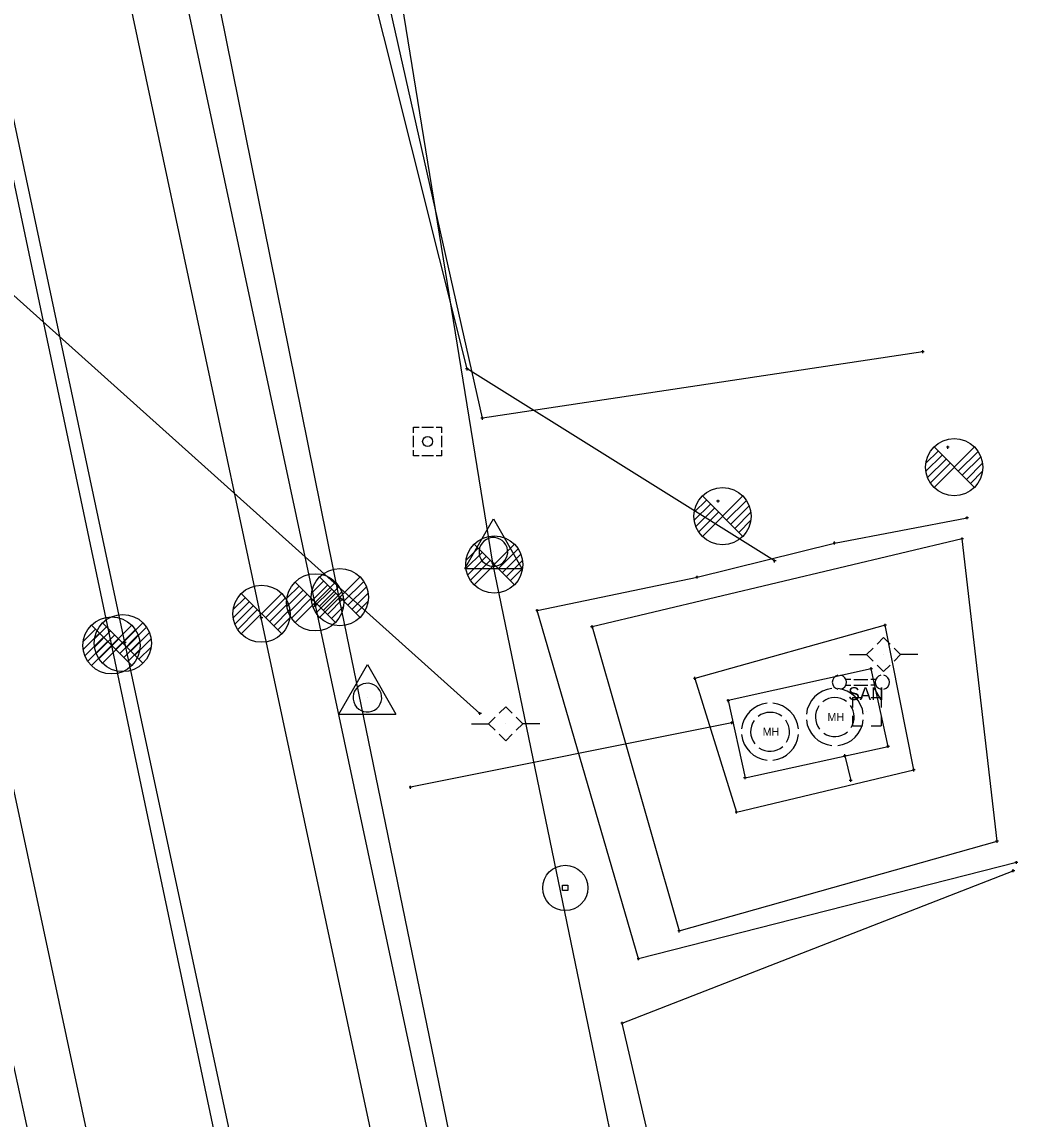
# Model space of a CAD drawing. Extents: x 1954856 to 2011933, y 399149 to 426294.
# Drawn here: x 2006043.9 to 2006132.7, y 402947.5 to 403043.4 of the extents above; entities that cross this region are included whole.
import ezdxf

# ---------------------------------------------------------------- set-up
doc = ezdxf.new("R2010")
doc.units = 0
for name, color, linetype in [('BankMent_ep', 7, 'Continuous'), ('BaselineSurvey', 7, 'Continuous'), ('ConcSlabs_ep', 7, 'Continuous'), ('ElecAer_ep', 7, 'Continuous'), ('Fence_ep', 7, 'Continuous'), ('Gates_ep', 7, 'Continuous'), ('ManholeUnknown_ep', 7, 'Continuous'), ('MonumentIRC_ep', 7, 'Continuous'), ('MonumentPIP_ep', 7, 'Continuous'), ('PavtAsphalt_ep', 7, 'Continuous'), ('PavtAsphaltCrown_ep', 7, 'Continuous'), ('PointLocator_ep', 7, 'Continuous'), ('PoleElec_ep', 7, 'Continuous'), ('PullBox_ep', 7, 'Continuous'), ('SanitarySewerB_ep', 7, 'Continuous'), ('ShldrPaved_ep', 7, 'Continuous'), ('TelePed_ep', 7, 'Continuous'), ('TreeLineWoods_ep', 7, 'Continuous'), ('VentSewer_ep', 7, 'Continuous'), ('XSPt_ep', 7, 'Continuous')]:
    doc.layers.add(name, color=color, linetype=linetype)

msp = doc.modelspace()

# ---------------------------------------------------------------- linework, layer by layer
at = {"layer": 'BankMent_ep'}
for points in [[(2006123.672, 402765.11), (2006120.281, 402798.882), (2006114.638, 402841.007), (2006105.234, 402898.319), (2006085.025, 402996.113), (2006069.006, 403095.019), (2006055.498, 403136.901)], [(2006121.666, 402755.96), (2006112.717, 402797.088), (2006091.828, 402894.752), (2006071.624, 402992.958), (2006051.855, 403090.735), (2006044.44, 403133.564)]]:
    msp.add_lwpolyline(points, dxfattribs=at)
for points in [[(2006093.704, 402990.551), (2006101.326, 402963.953), (2006129.111, 402971.79), (2006126.062, 402998.239)], [(2006102.683, 402986.036), (2006106.328, 402974.34), (2006121.837, 402978.026), (2006119.328, 402990.679)]]:
    msp.add_lwpolyline(points, close=True, dxfattribs=at)
at = {"layer": 'BaselineSurvey'}
msp.add_line((2006223.925, 402174.382), (2005094.479, 407516.047), dxfattribs=at)
msp.add_line((2006223.925, 402174.382), (2005094.479, 407516.047), dxfattribs=at)
at = {"layer": 'ConcSlabs_ep'}
msp.add_lwpolyline([(2006105.61, 402984.094), (2006107.079, 402977.35), (2006119.584, 402980.083), (2006118.106, 402986.881)], close=True, dxfattribs=at)
at = {"layer": 'ElecAer_ep'}
msp.add_lwpolyline([(2006062.406, 402767.04), (2006002.661, 403055.822), (2006083.898, 402982.967)], dxfattribs=at)
at = {"layer": 'Fence_ep'}
for points in [[(2006114.898, 402997.864), (2006126.489, 403000.07)], [(2006130.798, 402969.942), (2006097.759, 402961.511), (2006088.912, 402991.959), (2006102.89, 402994.885)]]:
    msp.add_lwpolyline(points, dxfattribs=at)
at = {"layer": 'Gates_ep'}
msp.add_lwpolyline([(2006102.89, 402994.885), (2006114.898, 402997.864)], dxfattribs=at)
at = {"layer": 'ManholeUnknown_ep'}
for p, q in [((2006114.927, 402982.652), (2006114.927, 402982.652)), ((2006109.265, 402981.366), (2006109.265, 402981.366))]:
    msp.add_line(p, q, dxfattribs=at)
for centre, radius, start, end in [((2006114.927, 402982.652), 2.5, 95.73916, 174.26084), ((2006114.927, 402982.652), 2.5, 5.73916, 84.26084), ((2006109.265, 402981.366), 2.5, 95.73916, 174.26084), ((2006109.265, 402981.366), 2.5, 5.73916, 84.26084), ((2006114.927, 402982.652), 1.7, 144.52453, 218.27924), ((2006114.927, 402982.652), 1.7, 53.11695, 127.61151), ((2006114.927, 402982.652), 1.7, 327.53021, 36.20393), ((2006109.265, 402981.366), 1.7, 53.11695, 127.61151), ((2006109.265, 402981.366), 1.7, 144.52453, 218.27924), ((2006109.265, 402981.366), 1.7, 327.53021, 36.20393), ((2006114.927, 402982.652), 2.5, 185.73916, 264.26084), ((2006114.927, 402982.652), 2.5, 275.73916, 354.26084), ((2006109.265, 402981.366), 2.5, 185.73916, 264.26084), ((2006109.265, 402981.366), 2.5, 275.73916, 354.26084), ((2006114.927, 402982.652), 1.7, 235.19226, 310.61719), ((2006109.265, 402981.366), 1.7, 235.19226, 310.61719)]:
    msp.add_arc(centre, radius, start, end, dxfattribs=at)
at = {"layer": 'MonumentIRC_ep'}
for p, q in [((2006082.573, 402995.651), (2006085.073, 402999.981)), ((2006085.073, 402999.981), (2006087.573, 402995.651)), ((2006085.073, 402997.094), (2006085.073, 402997.094)), ((2006082.573, 402995.651), (2006087.573, 402995.651)), ((2006071.559, 402982.91), (2006074.059, 402987.24)), ((2006074.059, 402987.24), (2006076.559, 402982.91)), ((2006074.059, 402984.353), (2006074.059, 402984.353)), ((2006071.559, 402982.91), (2006076.559, 402982.91))]:
    msp.add_line(p, q, dxfattribs=at)
for centre in [(2006085.073, 402997.094), (2006074.059, 402984.353)]:
    msp.add_arc(centre, 1.255, 209.92943, 209.02995, dxfattribs=at)
at = {"layer": 'MonumentPIP_ep'}
msp.add_line((2006091.361, 402967.713), (2006091.361, 402967.713), dxfattribs=at)
msp.add_lwpolyline([(2006091.129, 402967.481), (2006091.129, 402967.945), (2006091.593, 402967.945), (2006091.593, 402967.481)], close=True, dxfattribs=at)
msp.add_circle((2006091.361, 402967.713), 1.977, dxfattribs=at)
at = {"layer": 'PavtAsphalt_ep'}
msp.add_line((2006061.812, 402888.943), (2006040.75, 402987.463), dxfattribs=at)
msp.add_lwpolyline([(2006233.389, 402199.404), (2006231.307, 402208.776), (2006210.298, 402306.906), (2006189.726, 402404.406), (2006168.519, 402502.437), (2006147.449, 402600.546), (2006127.002, 402698.201), (2006106.479, 402795.475), (2006085.7, 402893.48), (2006064.781, 402991.322), (2006043.91, 403089.283), (2006023.047, 403187.504), (2006002.574, 403285.226), (2005981.704, 403382.697), (2005961.207, 403480.496), (2005940.446, 403578.305), (2005919.871, 403676.233), (2005898.845, 403774.26)], dxfattribs=at)
at = {"layer": 'PavtAsphaltCrown_ep'}
msp.add_lwpolyline([(2006221.576, 402197.041), (2006219.373, 402206.688), (2006198.419, 402304.427), (2006177.674, 402402.212), (2006156.488, 402500.143), (2006135.917, 402597.882), (2006115.394, 402695.489), (2006094.3, 402793.442), (2006073.801, 402891.433), (2006052.859, 402989.16), (2006032.075, 403086.962), (2006011.062, 403184.663), (2005990.583, 403282.628), (2005969.857, 403380.234), (2005949.302, 403478.326), (2005928.678, 403576.103), (2005908.104, 403674.029), (2005887.142, 403771.84)], dxfattribs=at)
at = {"layer": 'PointLocator_ep'}
for p, q in [((2006122.736, 403014.593), (2006122.486, 403014.593)), ((2006122.611, 403014.468), (2006122.611, 403014.718)), ((2006122.611, 403014.593), (2006122.611, 403014.593)), ((2006082.774, 403012.96), (2006082.774, 403013.21)), ((2006082.899, 403013.085), (2006082.649, 403013.085)), ((2006082.774, 403013.085), (2006082.774, 403013.085)), ((2006084.237, 403008.778), (2006083.987, 403008.778)), ((2006084.112, 403008.653), (2006084.112, 403008.903)), ((2006084.112, 403008.778), (2006084.112, 403008.778)), ((2006124.936, 403006.237), (2006124.686, 403006.237)), ((2006124.811, 403006.112), (2006124.811, 403006.362)), ((2006124.811, 403006.237), (2006124.811, 403006.237)), ((2006104.843, 403001.53), (2006104.593, 403001.53)), ((2006104.718, 403001.405), (2006104.718, 403001.655)), ((2006104.718, 403001.53), (2006104.718, 403001.53)), ((2006126.614, 403000.07), (2006126.364, 403000.07)), ((2006126.489, 402999.945), (2006126.489, 403000.195)), ((2006126.489, 403000.07), (2006126.489, 403000.07)), ((2006115.023, 402997.864), (2006114.773, 402997.864)), ((2006114.898, 402997.739), (2006114.898, 402997.989)), ((2006114.898, 402997.864), (2006114.898, 402997.864)), ((2006126.187, 402998.239), (2006125.937, 402998.239)), ((2006126.062, 402998.114), (2006126.062, 402998.364)), ((2006126.062, 402998.239), (2006126.062, 402998.239)), ((2006085.15, 402996.113), (2006084.9, 402996.113)), ((2006085.025, 402995.988), (2006085.025, 402996.238)), ((2006085.025, 402996.113), (2006085.025, 402996.113)), ((2006109.787, 402996.303), (2006109.537, 402996.303)), ((2006109.662, 402996.178), (2006109.662, 402996.428)), ((2006109.662, 402996.303), (2006109.662, 402996.303)), ((2006102.89, 402994.76), (2006102.89, 402995.01)), ((2006103.015, 402994.885), (2006102.765, 402994.885)), ((2006102.89, 402994.885), (2006102.89, 402994.885)), ((2006071.624, 402992.833), (2006071.624, 402993.083)), ((2006069.654, 402992.446), (2006069.404, 402992.446)), ((2006069.529, 402992.321), (2006069.529, 402992.571)), ((2006069.529, 402992.446), (2006069.529, 402992.446)), ((2006071.749, 402992.958), (2006071.499, 402992.958)), ((2006071.624, 402992.958), (2006071.624, 402992.958)), ((2006088.912, 402991.834), (2006088.912, 402992.084)), ((2006064.906, 402991.322), (2006064.656, 402991.322)), ((2006064.781, 402991.197), (2006064.781, 402991.447)), ((2006064.781, 402991.322), (2006064.781, 402991.322)), ((2006089.037, 402991.959), (2006088.787, 402991.959)), ((2006088.912, 402991.959), (2006088.912, 402991.959)), ((2006093.829, 402990.551), (2006093.579, 402990.551)), ((2006093.704, 402990.426), (2006093.704, 402990.676)), ((2006093.704, 402990.551), (2006093.704, 402990.551)), ((2006119.453, 402990.679), (2006119.203, 402990.679)), ((2006119.328, 402990.554), (2006119.328, 402990.804)), ((2006119.328, 402990.679), (2006119.328, 402990.679)), ((2006052.859, 402989.035), (2006052.859, 402989.285)), ((2006052.984, 402989.16), (2006052.734, 402989.16)), ((2006052.859, 402989.16), (2006052.859, 402989.16)), ((2006118.231, 402986.881), (2006117.981, 402986.881)), ((2006118.106, 402986.756), (2006118.106, 402987.006)), ((2006118.106, 402986.881), (2006118.106, 402986.881)), ((2006102.808, 402986.036), (2006102.558, 402986.036)), ((2006102.683, 402985.911), (2006102.683, 402986.161)), ((2006102.683, 402986.036), (2006102.683, 402986.036)), ((2006105.735, 402984.094), (2006105.485, 402984.094)), ((2006105.61, 402983.969), (2006105.61, 402984.219)), ((2006105.61, 402984.094), (2006105.61, 402984.094)), ((2006084.023, 402982.967), (2006083.773, 402982.967)), ((2006083.898, 402982.842), (2006083.898, 402983.092)), ((2006083.898, 402982.967), (2006083.898, 402982.967)), ((2006106.042, 402982.146), (2006105.792, 402982.146)), ((2006105.917, 402982.021), (2006105.917, 402982.271)), ((2006105.917, 402982.146), (2006105.917, 402982.146)), ((2006119.709, 402980.083), (2006119.459, 402980.083)), ((2006119.584, 402979.958), (2006119.584, 402980.208)), ((2006119.584, 402980.083), (2006119.584, 402980.083)), ((2006115.934, 402979.272), (2006115.684, 402979.272)), ((2006115.809, 402979.147), (2006115.809, 402979.397)), ((2006115.809, 402979.272), (2006115.809, 402979.272)), ((2006121.962, 402978.026), (2006121.712, 402978.026)), ((2006121.837, 402977.901), (2006121.837, 402978.151)), ((2006121.837, 402978.026), (2006121.837, 402978.026)), ((2006107.204, 402977.35), (2006106.954, 402977.35)), ((2006107.079, 402977.225), (2006107.079, 402977.475)), ((2006107.079, 402977.35), (2006107.079, 402977.35)), ((2006116.437, 402977.108), (2006116.187, 402977.108)), ((2006116.312, 402976.983), (2006116.312, 402977.233)), ((2006116.312, 402977.108), (2006116.312, 402977.108)), ((2006077.963, 402976.512), (2006077.713, 402976.512)), ((2006077.838, 402976.387), (2006077.838, 402976.637)), ((2006077.838, 402976.512), (2006077.838, 402976.512)), ((2006106.453, 402974.34), (2006106.203, 402974.34)), ((2006106.328, 402974.215), (2006106.328, 402974.465)), ((2006106.328, 402974.34), (2006106.328, 402974.34)), ((2006129.236, 402971.79), (2006128.986, 402971.79)), ((2006129.111, 402971.665), (2006129.111, 402971.915)), ((2006129.111, 402971.79), (2006129.111, 402971.79)), ((2006130.798, 402969.817), (2006130.798, 402970.067)), ((2006130.65, 402969.223), (2006130.4, 402969.223)), ((2006130.525, 402969.098), (2006130.525, 402969.348)), ((2006130.525, 402969.223), (2006130.525, 402969.223)), ((2006130.923, 402969.942), (2006130.673, 402969.942)), ((2006130.798, 402969.942), (2006130.798, 402969.942)), ((2006101.451, 402963.953), (2006101.201, 402963.953)), ((2006101.326, 402963.828), (2006101.326, 402964.078)), ((2006101.326, 402963.953), (2006101.326, 402963.953)), ((2006097.884, 402961.511), (2006097.634, 402961.511)), ((2006097.759, 402961.386), (2006097.759, 402961.636)), ((2006097.759, 402961.511), (2006097.759, 402961.511)), ((2006096.474, 402955.89), (2006096.224, 402955.89)), ((2006096.349, 402955.765), (2006096.349, 402956.015)), ((2006096.349, 402955.89), (2006096.349, 402955.89))]:
    msp.add_line(p, q, dxfattribs=at)
at = {"layer": 'PoleElec_ep'}
for p, q in [((2006117.699, 402988.11), (2006118.266, 402988.677)), ((2006116.199, 402988.11), (2006117.699, 402988.11)), ((2006118.266, 402987.543), (2006117.699, 402988.11)), ((2006119.187, 402988.11), (2006119.187, 402988.11)), ((2006122.175, 402988.11), (2006120.675, 402988.11)), ((2006084.662, 402982.065), (2006085.229, 402982.632)), ((2006083.162, 402982.065), (2006084.662, 402982.065)), ((2006085.229, 402981.498), (2006084.662, 402982.065)), ((2006086.15, 402982.065), (2006086.15, 402982.065)), ((2006089.138, 402982.065), (2006087.638, 402982.065))]:
    msp.add_line(p, q, dxfattribs=at)
for points in [[(2006118.62, 402989.031), (2006119.187, 402989.598), (2006119.754, 402989.031)], [(2006120.108, 402988.677), (2006120.675, 402988.11), (2006120.108, 402987.543)], [(2006119.754, 402987.189), (2006119.187, 402986.622), (2006118.62, 402987.189)], [(2006085.583, 402982.986), (2006086.15, 402983.553), (2006086.717, 402982.986)], [(2006087.071, 402982.632), (2006087.638, 402982.065), (2006087.071, 402981.498)], [(2006086.717, 402981.144), (2006086.15, 402980.577), (2006085.583, 402981.144)]]:
    msp.add_lwpolyline(points, dxfattribs=at)
at = {"layer": 'PullBox_ep'}
for p, q in [((2006116.482, 402984.376), (2006116.482, 402983.501)), ((2006116.482, 402984.376), (2006117.357, 402984.376)), ((2006118.107, 402984.376), (2006118.982, 402984.376)), ((2006118.982, 402984.376), (2006118.982, 402983.501)), ((2006116.482, 402982.751), (2006116.482, 402981.876)), ((2006117.732, 402983.126), (2006117.732, 402983.126)), ((2006118.982, 402982.751), (2006118.982, 402981.876)), ((2006116.482, 402981.876), (2006117.357, 402981.876)), ((2006118.107, 402981.876), (2006118.982, 402981.876))]:
    msp.add_line(p, q, dxfattribs=at)
at = {"layer": 'SanitarySewerB_ep'}
for points in [[(2006109.662, 402996.303), (2006082.774, 403013.085), (2006070.623, 403061.586), (2006059.539, 403110.342), (2006049.569, 403183.745), (2006069.387, 403186.436)], [(2006105.917, 402982.146), (2006077.838, 402976.512)], [(2006115.809, 402979.272), (2006116.312, 402977.108)]]:
    msp.add_lwpolyline(points, dxfattribs=at)
at = {"layer": 'ShldrPaved_ep'}
msp.add_line((2006057.174, 402887.717), (2006043.151, 402952.168), dxfattribs=at)
msp.add_lwpolyline([(2006236.969, 402200.287), (2006234.962, 402209.437), (2006223.134, 402265.913), (2006222.91, 402271.947), (2006207.492, 402343.568), (2006194.34, 402405.594), (2006173.46, 402503.371), (2006152.82, 402601.72), (2006132.252, 402699.305), (2006111.086, 402796.876), (2006090.393, 402894.562), (2006069.529, 402992.446), (2006048.695, 403090.064), (2006039.794, 403131.914), (2006031.777, 403169.965), (2006021.65, 403217.639), (2006000.244, 403320.058), (2005986.359, 403383.796), (2005966.07, 403481.267), (2005945.248, 403579.603), (2005942.285, 403592.899), (2005924.794, 403677.386), (2005916.053, 403717.643), (2005903.415, 403775.167)], dxfattribs=at)
at = {"layer": 'TelePed_ep'}
for p, q in [((2006078.078, 403007.992), (2006078.578, 403007.992)), ((2006078.078, 403007.492), (2006078.078, 403007.992)), ((2006078.828, 403007.992), (2006079.828, 403007.992)), ((2006080.078, 403007.992), (2006080.578, 403007.992)), ((2006080.578, 403007.492), (2006080.578, 403007.992)), ((2006078.078, 403006.242), (2006078.078, 403007.242)), ((2006079.328, 403006.742), (2006079.328, 403006.742)), ((2006080.578, 403006.242), (2006080.578, 403007.242)), ((2006078.078, 403005.492), (2006078.078, 403005.992)), ((2006080.578, 403005.492), (2006080.578, 403005.992)), ((2006078.578, 403005.492), (2006078.078, 403005.492)), ((2006079.828, 403005.492), (2006078.828, 403005.492)), ((2006080.578, 403005.492), (2006080.078, 403005.492))]:
    msp.add_line(p, q, dxfattribs=at)
msp.add_circle((2006079.328, 403006.742), 0.438, dxfattribs=at)
at = {"layer": 'TreeLineWoods_ep'}
for points in [[(2006122.611, 403014.593), (2006084.112, 403008.778), (2006064.963, 403093.773), (2006059.12, 403138.498), (2006096.899, 403138.892)], [(2006243.605, 402429.584), (2006206.994, 402425.43), (2006192.074, 402507.768), (2006173.071, 402606.222), (2006151.272, 402703.221), (2006131.236, 402800.8), (2006109.605, 402898.993), (2006096.349, 402955.89), (2006130.525, 402969.223)]]:
    msp.add_lwpolyline(points, dxfattribs=at)
at = {"layer": 'VentSewer_ep'}
for p, q in [((2006116.327, 402985.949), (2006115.9, 402985.949)), ((2006115.9, 402985.449), (2006116.327, 402985.449)), ((2006116.577, 402985.949), (2006117.827, 402985.949)), ((2006116.577, 402985.449), (2006117.827, 402985.449)), ((2006117.202, 402985.699), (2006117.202, 402985.699)), ((2006118.504, 402985.949), (2006118.077, 402985.949)), ((2006118.504, 402985.449), (2006118.077, 402985.449))]:
    msp.add_line(p, q, dxfattribs=at)
for centre, start, end in [((2006115.327, 402985.699), 101.53696, 258.62128), ((2006115.327, 402985.699), 281.6952, 78.46304), ((2006119.077, 402985.699), 101.53696, 257.76687), ((2006119.077, 402985.699), 281.53696, 78.46304)]:
    msp.add_arc(centre, 0.625, start, end, dxfattribs=at)
at = {"layer": 'XSPt_ep'}
for p, q in [((2006122.891, 403004.85), (2006123.952, 403005.91)), ((2006122.891, 403004.142), (2006124.305, 403005.557)), ((2006123.598, 403002.728), (2006127.134, 403006.264)), ((2006127.134, 403002.728), (2006123.598, 403006.264)), ((2006125.72, 403004.142), (2006127.452, 403005.874)), ((2006123.039, 403003.583), (2006124.659, 403005.203)), ((2006123.28, 403003.118), (2006125.012, 403004.85)), ((2006126.073, 403003.789), (2006127.693, 403005.409)), ((2006126.427, 403003.435), (2006127.841, 403004.85)), ((2006125.366, 403004.496), (2006125.366, 403004.496)), ((2006126.78, 403003.082), (2006127.841, 403004.142)), ((2006103.346, 402998.445), (2006106.882, 403001.981)), ((2006106.882, 402998.445), (2006103.346, 403001.981)), ((2006102.639, 403000.567), (2006103.7, 403001.627)), ((2006102.639, 402999.859), (2006104.053, 403001.274)), ((2006102.787, 402999.3), (2006104.407, 403000.92)), ((2006105.468, 402999.859), (2006107.2, 403001.591)), ((2006105.821, 402999.506), (2006107.441, 403001.126)), ((2006103.028, 402998.835), (2006104.76, 403000.567)), ((2006105.114, 403000.213), (2006105.114, 403000.213)), ((2006106.175, 402999.152), (2006107.589, 403000.567)), ((2006106.528, 402998.799), (2006107.589, 402999.859)), ((2006082.68, 402996.347), (2006083.741, 402997.407)), ((2006082.68, 402995.639), (2006084.094, 402997.054)), ((2006083.387, 402994.225), (2006086.923, 402997.761)), ((2006086.923, 402994.225), (2006083.387, 402997.761)), ((2006085.509, 402995.639), (2006087.241, 402997.371)), ((2006085.862, 402995.286), (2006087.482, 402996.906)), ((2006082.828, 402995.08), (2006084.448, 402996.7)), ((2006083.069, 402994.615), (2006084.801, 402996.347)), ((2006085.155, 402995.993), (2006085.155, 402995.993)), ((2006086.216, 402994.932), (2006087.63, 402996.347)), ((2006086.569, 402994.579), (2006087.63, 402995.639)), ((2006067.026, 402993.037), (2006068.087, 402994.097)), ((2006067.733, 402990.915), (2006071.269, 402994.451)), ((2006071.269, 402990.915), (2006067.733, 402994.451)), ((2006069.179, 402993.493), (2006070.24, 402994.553)), ((2006069.179, 402992.785), (2006070.593, 402994.2)), ((2006069.855, 402992.329), (2006071.587, 402994.061)), ((2006069.886, 402991.371), (2006073.422, 402994.907)), ((2006073.422, 402991.371), (2006069.886, 402994.907)), ((2006072.008, 402992.785), (2006073.74, 402994.517)), ((2006072.361, 402992.432), (2006073.981, 402994.052)), ((2006062.33, 402992.045), (2006063.391, 402993.105)), ((2006063.037, 402989.923), (2006066.573, 402993.459)), ((2006066.573, 402989.923), (2006063.037, 402993.459)), ((2006065.159, 402991.337), (2006066.891, 402993.069)), ((2006067.026, 402992.329), (2006068.44, 402993.744)), ((2006067.174, 402991.77), (2006068.794, 402993.39)), ((2006067.415, 402991.305), (2006069.147, 402993.037)), ((2006069.327, 402992.226), (2006070.947, 402993.846)), ((2006069.568, 402991.761), (2006071.3, 402993.493)), ((2006070.208, 402991.976), (2006071.828, 402993.596)), ((2006070.562, 402991.622), (2006071.976, 402993.037)), ((2006071.654, 402993.139), (2006071.654, 402993.139)), ((2006072.715, 402992.078), (2006074.129, 402993.493)), ((2006062.33, 402991.337), (2006063.744, 402992.752)), ((2006062.478, 402990.778), (2006064.098, 402992.398)), ((2006065.512, 402990.984), (2006067.132, 402992.604)), ((2006069.501, 402992.683), (2006069.501, 402992.683)), ((2006070.915, 402991.269), (2006071.976, 402992.329)), ((2006073.068, 402991.725), (2006074.129, 402992.785)), ((2006062.719, 402990.313), (2006064.451, 402992.045)), ((2006064.805, 402991.691), (2006064.805, 402991.691)), ((2006065.866, 402990.63), (2006067.28, 402992.045)), ((2006066.219, 402990.277), (2006067.28, 402991.337)), ((2006049.22, 402989.272), (2006050.281, 402990.332)), ((2006049.927, 402987.15), (2006053.463, 402990.686)), ((2006053.463, 402987.15), (2006049.927, 402990.686)), ((2006050.198, 402989.479), (2006051.259, 402990.539)), ((2006050.198, 402988.771), (2006051.612, 402990.186)), ((2006050.905, 402987.357), (2006054.441, 402990.893)), ((2006054.441, 402987.357), (2006050.905, 402990.893)), ((2006052.049, 402988.564), (2006053.781, 402990.296)), ((2006053.027, 402988.771), (2006054.759, 402990.503)), ((2006049.22, 402988.564), (2006050.634, 402989.979)), ((2006049.368, 402988.005), (2006050.988, 402989.625)), ((2006049.609, 402987.54), (2006051.341, 402989.272)), ((2006050.346, 402988.212), (2006051.966, 402989.832)), ((2006050.587, 402987.747), (2006052.319, 402989.479)), ((2006052.402, 402988.211), (2006054.022, 402989.831)), ((2006052.756, 402987.857), (2006054.17, 402989.272)), ((2006053.38, 402988.418), (2006055, 402990.038)), ((2006053.734, 402988.064), (2006055.148, 402989.479)), ((2006051.695, 402988.918), (2006051.695, 402988.918)), ((2006052.673, 402989.125), (2006052.673, 402989.125)), ((2006053.109, 402987.504), (2006054.17, 402988.564)), ((2006054.087, 402987.711), (2006055.148, 402988.771))]:
    msp.add_line(p, q, dxfattribs=at)
for centre in [(2006125.366, 403004.496), (2006105.114, 403000.213), (2006085.155, 402995.993), (2006069.501, 402992.683), (2006071.654, 402993.139), (2006064.805, 402991.691), (2006051.695, 402988.918), (2006052.673, 402989.125)]:
    msp.add_circle(centre, 2.5, dxfattribs=at)

# ---------------------------------------------------------------- texts
at = {"layer": 'ManholeUnknown_ep'}
for p in [(2006114.278, 402982.302), (2006108.616, 402981.016)]:
    msp.add_text('MH', height=0.7, dxfattribs=at).set_placement(p)
at = {"layer": 'VentSewer_ep'}
msp.add_text('SAN', height=1.125, dxfattribs=at).set_placement((2006116.098, 402984.137))

doc.saveas('drawing.dxf')
